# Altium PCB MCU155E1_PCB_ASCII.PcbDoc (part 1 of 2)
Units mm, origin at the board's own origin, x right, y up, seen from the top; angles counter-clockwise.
Board outline 32 x 29 mm, 4 copper layers (Top Layer, Layer 1, Layer 2, Bottom Layer), stack 1.567 mm thick; 102 components, 61 nets, 283 pads, 120 vias.
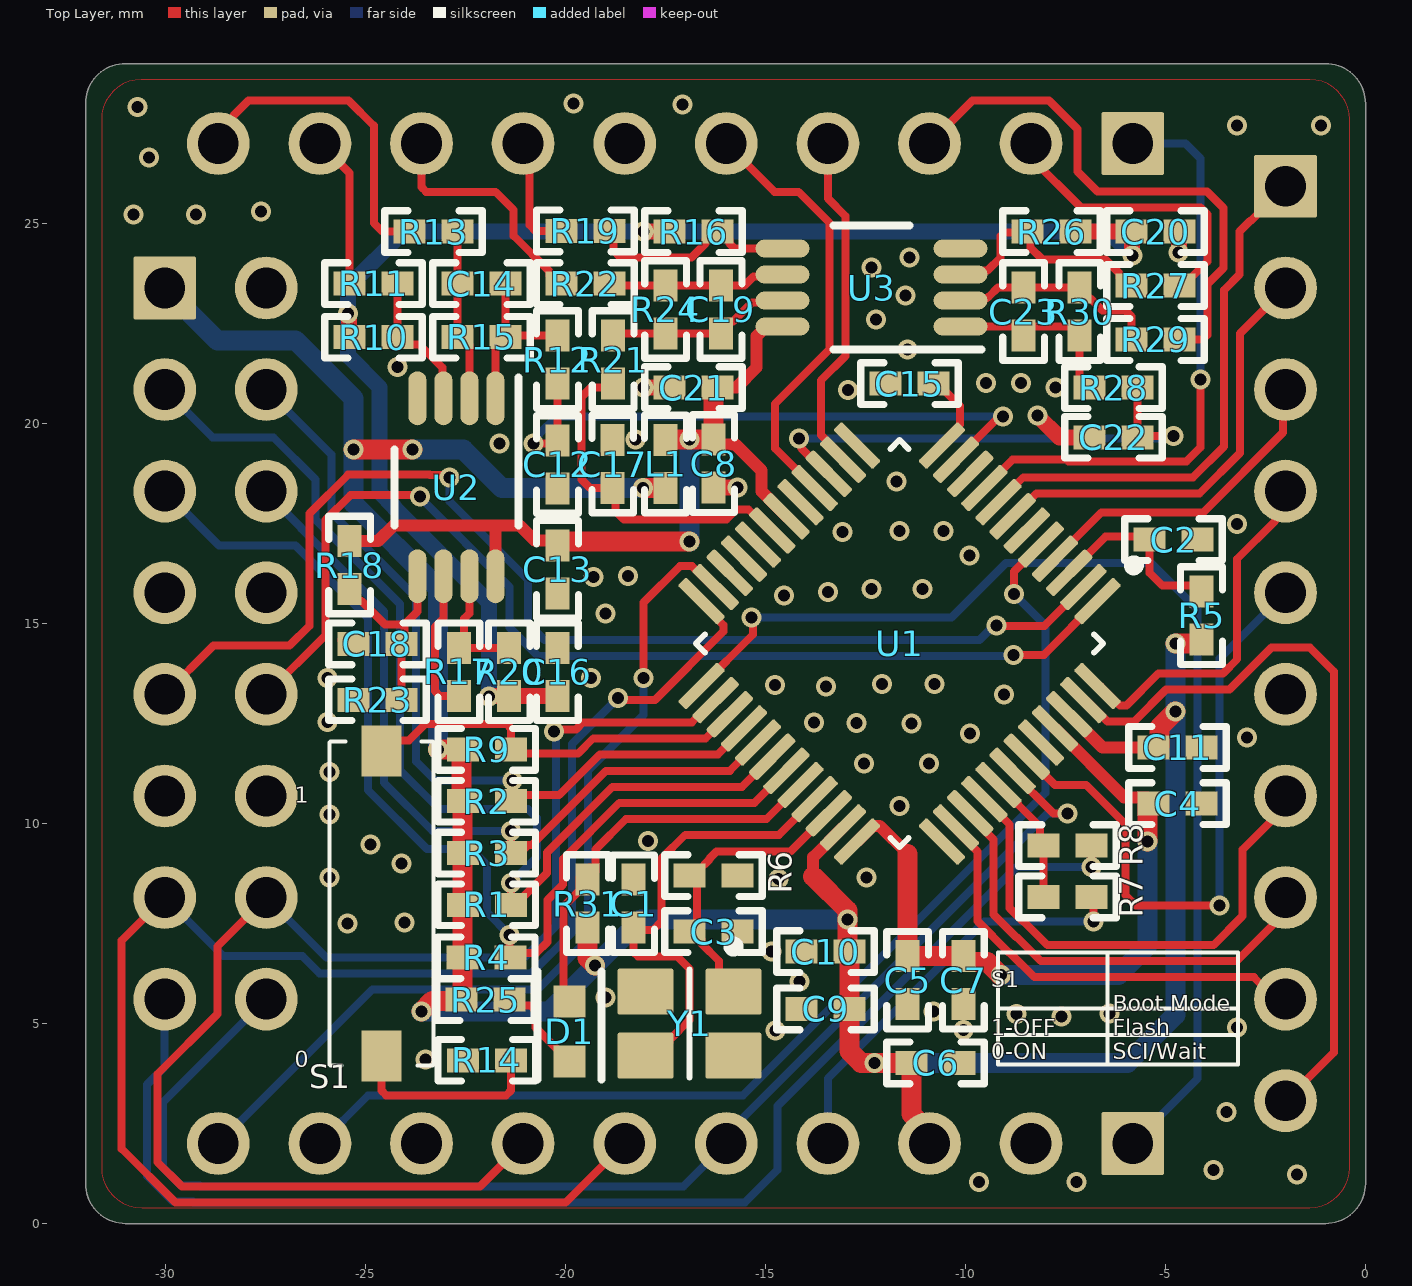
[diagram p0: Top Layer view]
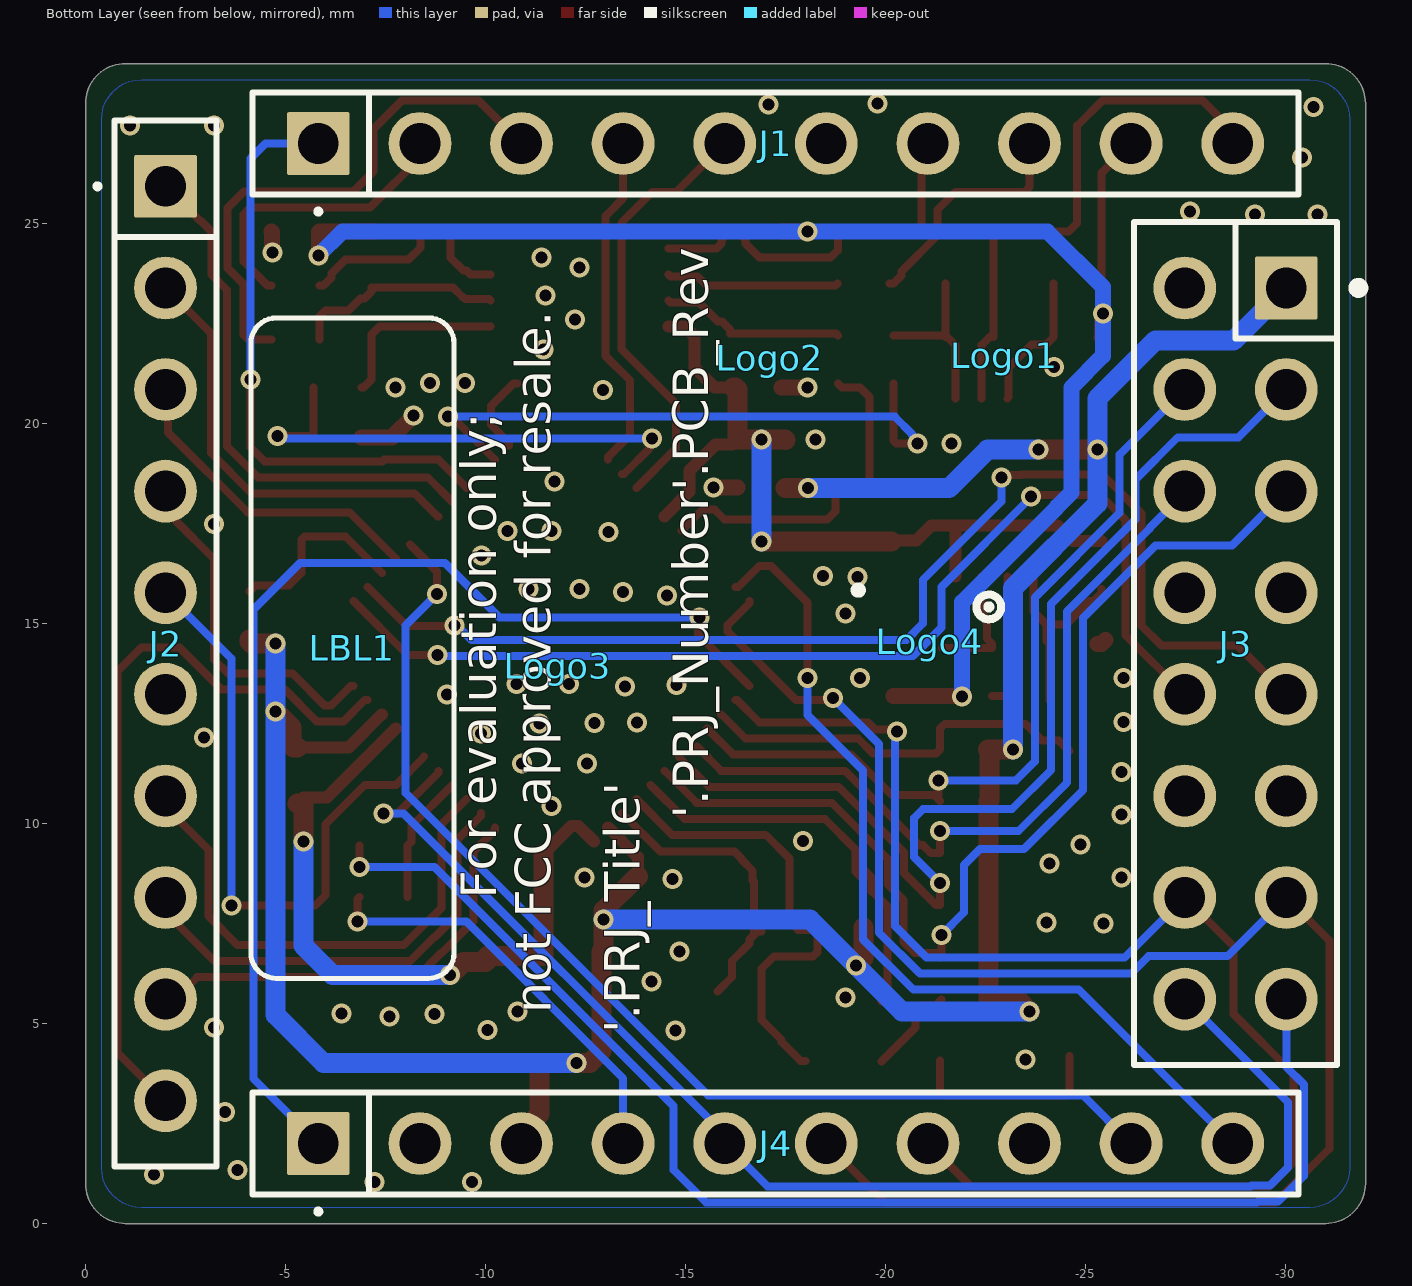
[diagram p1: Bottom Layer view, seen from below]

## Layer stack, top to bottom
Top Solder: solder mask 0.0102, Solder Resist, Dk 3.5
Top Layer: signal copper 0.035
Dielectric 1: prepreg 0.2184, PP-023, Dk 4.5
Layer 1: signal copper 0.035
Dielectric1: core 0.9906, Core-042, Dk 4.6
Layer 2: signal copper 0.035
Dielectric 2: prepreg 0.2184, PP-023, Dk 4.5
Bottom Layer: signal copper 0.035
Bottom Solder: solder mask 0.0102, Solder Resist, Dk 3.5

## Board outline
-32,1 -32,28 cw(c-31,28) -31,29 -1,29 cw(c-1,28) 0,28 0,1 cw(c-1,1) -1,0 -31,0 cw(c-31,1)

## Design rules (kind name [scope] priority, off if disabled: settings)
AcuteAngle [All] p0: scope1count=1 scope1_0_kind=Board scope1_0_value=Board scope2count=1 scope2_0_kind=Board scope2_0_value=Board commentlength=0 minimum=4.50000000000000E+0001
AcuteAngle [All] p1: minimum=4.50000000000000E+0001 checktracksonly=FALSE
AssemblyTestPointUsage [All] p0: scope1count=1 scope1_0_kind=Board scope1_0_value=Board scope2count=1 scope2_0_kind=Board scope2_0_value=Board commentlength=0
AssemblyTestPointUsage [All] p1: valid=2
AssemblyTestpoint [All] p0: scope1count=1 scope1_0_kind=Board scope1_0_value=Board scope2count=1 scope2_0_kind=Board scope2_0_value=Board commentlength=0
BoardOutlineClearance [All] p0 off: scope1count=1 scope1_0_kind=Board scope1_0_value=Board scope2count=1 scope2_0_kind=Board scope2_0_value=Board commentlength=172 gap=0 // Protel DXP Scope 1 Expression Was: OnCopper and Not InComponentClass('Logo') and not InComponentClass('FiducialMark') and not InRegion(1000,500,4000,800) and not InPoly
BoardOutlineClearance BoardOutlineClearance_Poly [All] p0 off: scope1count=1 scope1_0_kind=Board scope1_0_value=Board scope2count=1 scope2_0_kind=Board scope2_0_value=Board commentlength=58 gap=0 // Protel DXP Scope 1 Expression Was: OnCopper and IsPoly
BoardOutlineClearance BoardOutlineClearance_MountingHoles [All] p0 off: scope1count=1 scope1_0_kind=Board scope1_0_value=Board scope2count=1 scope2_0_kind=Board scope2_0_value=Board commentlength=86 gap=0 // Protel DXP Scope 1 Expression Was: OnCopper and InComponentClass('Mounting Holes')
BoardOutlineClearance BoardOutlineClearance_MountingHoles [OnCopper and InComponentClass('Mounting Holes')] p1: gap=0 ignorepadtopadclearanceinfootprint=FALSE
BoardOutlineClearance BoardOutlineClearance_Poly [OnCopper and IsPoly] p2: gap=0 ignorepadtopadclearanceinfootprint=FALSE
BoardOutlineClearance [OnCopper and Not InComponentClass('Logo') and not InComponentClass('FiducialMark') and not InRegion(1000,500,4000,800) and not InPoly] p3: gap=0 ignorepadtopadclearanceinfootprint=FALSE
Clearance Clearance_1 [All] p0 off: scope1count=1 scope1_0_kind=Board scope1_0_value=Board scope2count=1 scope2_0_kind=Board scope2_0_value=Board commentlength=160 gap=0.19 // Protel DXP Scope 1 Expression Was: (InComponent('J1') or InComponent('J2') or InComponent('J3') or InComponent('J4') ) and not HasFootprint('fiducial10-20')
Clearance [All] p0 off: scope1count=1 scope1_0_kind=Board scope1_0_value=Board scope2count=1 scope2_0_kind=Board scope2_0_value=Board commentlength=159 gap=0.2 // Protel DXP Scope 2 Expression Was: not HasFootprint('fiducial10-20') or (InComponent('J1') or InComponent('J2') or InComponent('J3') or InComponent('J4') )
Clearance SMTPadToTHHole [All] p0 off: scope1count=1 scope1_0_kind=Board scope1_0_value=Board scope2count=1 scope2_0_kind=Board scope2_0_value=Board commentlength=115 gap=0.15 // Protel DXP Scope 2 Expression Was: InSMTComponent and OnLayer('Bottom Layer') and not HasFootprint('TP_SM_1MM')
Clearance PB+ToPB- [All] p0: scope1count=1 scope1_0_kind=NetClass scope1_0_value=HV scope2count=1 scope2_0_kind=NetClass scope2_0_value=LV_Signal commentlength=0 gap=3
Clearance PB+ToACN [All] p0: scope1count=1 scope1_0_kind=NetClass scope1_0_value=V_BUS scope2count=1 scope2_0_kind=NetClass scope2_0_value=ACN commentlength=0 gap=1.5
Clearance PB+ToACL [All] p0: scope1count=1 scope1_0_kind=NetClass scope1_0_value=V_BUS scope2count=1 scope2_0_kind=NetClass scope2_0_value=ACL commentlength=0 gap=3
Clearance PB-ToACL [All] p0: scope1count=1 scope1_0_kind=NetClass scope1_0_value="LV Signal" scope2count=1 scope2_0_kind=NetClass scope2_0_value=ACL commentlength=0 gap=3
Clearance ISOToAll [All] p0 off: scope1count=1 scope1_0_kind=NetClass scope1_0_value=Isolation scope2count=1 scope2_0_kind=Board scope2_0_value=Board commentlength=105 gap=6 // Protel DXP Scope 2 Expression Was: not InNetClass('Isolation')   and (not  OnLayer('Keep-Out Layer'))
Clearance ACLToACN [All] p0: scope1count=1 scope1_0_kind=NetClass scope1_0_value=ACL scope2count=1 scope2_0_kind=NetClass scope2_0_value=ACN commentlength=0 gap=2
Clearance PB-ToACN [All] p0: scope1count=1 scope1_0_kind=NetClass scope1_0_value="LV Signal" scope2count=1 scope2_0_kind=NetClass scope2_0_value=ACN commentlength=0 gap=3
Clearance Clearance_1 [(InComponent('J1') or InComponent('J2') or InComponent('J3') or InComponent('J4') ) and not HasFootprint('fiducial10-20')] p1: gap=0.19 ignorepadtopadclearanceinfootprint=TRUE
Clearance PB+ToPB- [InNetClass('HV') vs InNetClass('LV_Signal')] p2: gap=3 ignorepadtopadclearanceinfootprint=TRUE
Clearance PB-ToACN [InNetClass('LV Signal') vs InNetClass('ACN')] p3: gap=3 ignorepadtopadclearanceinfootprint=TRUE
Clearance ACLToACN [InNetClass('ACL') vs InNetClass('ACN')] p4: gap=2 ignorepadtopadclearanceinfootprint=FALSE
Clearance ISOToAll [InNetClass('Isolation') vs not InNetClass('Isolation')   and (not  OnLayer('Keep-Out Layer'))] p5: gap=6 ignorepadtopadclearanceinfootprint=TRUE
Clearance PB-ToACL [InNetClass('LV Signal') vs InNetClass('ACL')] p6: gap=3 ignorepadtopadclearanceinfootprint=TRUE
Clearance PB+ToACL [InNetClass('V_BUS') vs InNetClass('ACL')] p7: gap=3 ignorepadtopadclearanceinfootprint=TRUE
Clearance PB+ToACN [InNetClass('V_BUS') vs InNetClass('ACN')] p8: gap=1.5 ignorepadtopadclearanceinfootprint=TRUE
Clearance SMTPadToTHHole [not IsVia and OnLayer('Multi-Layer') and not InComponent('J1') and not InComponent('J2') and not InComponent('J3') and not InComponent('J4') and not InComponent('J12') and PadIsPlated vs InSMTComponent and OnLayer('Bottom Layer') and not HasFootprint('TP_SM_1MM')] p9: gap=0.15 ignorepadtopadclearanceinfootprint=FALSE except(3: SMDPad-THPad)
Clearance [All vs not HasFootprint('fiducial10-20') or (InComponent('J1') or InComponent('J2') or InComponent('J3') or InComponent('J4') )] p10: gap=0.2 ignorepadtopadclearanceinfootprint=TRUE
ComponentClearance [All] p0: scope1count=1 scope1_0_kind=Board scope1_0_value=Board scope2count=1 scope2_0_kind=Board scope2_0_value=Board commentlength=0 gap=0.508 collisioncheckmode=3
ComponentClearance ComponentClearance_THtoTH [All] p0 off: scope1count=1 scope1_0_kind=Board scope1_0_value=Board scope2count=1 scope2_0_kind=Board scope2_0_value=Board commentlength=54 gap=0.508 collisioncheckmode=3 // Protel DXP Scope 2 Expression Was: IsThruComponent
ComponentClearance ComponentClearance_THtoSMT [All] p0 off: scope1count=1 scope1_0_kind=Board scope1_0_value=Board scope2count=1 scope2_0_kind=Board scope2_0_value=Board commentlength=53 gap=0.762 collisioncheckmode=3 // Protel DXP Scope 2 Expression Was: IsSMTComponent
ComponentClearance ComponentClearance_SmallPassives [All] p0 off: scope1count=1 scope1_0_kind=Board scope1_0_value=Board scope2count=1 scope2_0_kind=Board scope2_0_value=Board commentlength=508 gap=0.38 collisioncheckmode=3 // Protel DXP Scope 2 Expression Was: HasFootprint('0201*') or HasFootprint('0402*') or HasFootprint('0508') or HasFootprint('0603*') or HasFootprint('0612') or HasFootprint('0805*') or HasFootprint('0815*') or HasFootprint('0830*') or HasFootprint('1206*') or HasFootprint('1210*') or HasFootprint('1808*') or HasFootprint('1812*') or HasFootprint('1825*') or HasFootprint('2010*') or HasFootprint('2220*') or HasFootprint('2225*') or HasFootprint('2512*') or HasFootprint('2728*') or HasFootprint('3518*')
ComponentClearance ComponentClearance_MountingHoles [All] p0: scope1count=1 scope1_0_kind=ComponentClass scope1_0_value="Mounting Holes" scope2count=1 scope2_0_kind=Board scope2_0_value=Board commentlength=0 gap=2.54 collisioncheckmode=3
ComponentClearance ComponentClearance_ScrewToNut [All] p0 off: scope1count=1 scope1_0_kind=Board scope1_0_value=Board scope2count=1 scope2_0_kind=Board scope2_0_value=Board commentlength=71 gap=0.127 collisioncheckmode=3 // Protel DXP Scope 2 Expression Was: (HasFootprint('Keystone_1902C'))
ComponentClearance ComponentClearance_Logo [All] p0: scope1count=1 scope1_0_kind=ComponentClass scope1_0_value=Logo scope2count=1 scope2_0_kind=Board scope2_0_value=Board commentlength=0 gap=0.762 collisioncheckmode=3
ComponentClearance ComponentClearance_Shunt [All] p0: scope1count=1 scope1_0_kind=ComponentClass scope1_0_value=Header scope2count=1 scope2_0_kind=ComponentClass scope2_0_value=Shunt commentlength=0 gap=0 collisioncheckmode=3
ComponentClearance ComponentClearance_MountingHoles_FiducialMarks [All] p0: scope1count=1 scope1_0_kind=ComponentClass scope1_0_value="Mounting Holes" scope2count=1 scope2_0_kind=ComponentClass scope2_0_value=FiducialMark commentlength=0 gap=1.27 collisioncheckmode=3
ComponentClearance ComponentClearance_MountingHoles_FiducialMarks [InComponentClass('Mounting Holes') vs InComponentClass('FiducialMark')] p1: gap=1.27 collisioncheckmode=3 verticalgap=0.254 showdistances=FALSE
ComponentClearance ComponentClearance_Shunt [InComponentClass('Header') vs InComponentClass('Shunt')] p2: gap=0 collisioncheckmode=3 verticalgap=0 showdistances=FALSE
ComponentClearance ComponentClearance_Logo [InComponentClass('Logo')] p3: gap=0.762 collisioncheckmode=3 verticalgap=0.254 showdistances=FALSE
ComponentClearance ComponentClearance_ScrewToNut [(HasFootprint('NY PMS 440 0025 PH')) vs (HasFootprint('Keystone_1902C'))] p4: gap=0.127 collisioncheckmode=3 verticalgap=0.254 showdistances=FALSE
ComponentClearance ComponentClearance_MountingHoles [InComponentClass('Mounting Holes')] p5: gap=2.54 collisioncheckmode=3 verticalgap=2540 showdistances=FALSE
ComponentClearance ComponentClearance_SmallPassives [HasFootprint('0201*') or HasFootprint('0402*') or HasFootprint('0508') or HasFootprint('0603*') or HasFootprint('0612') or HasFootprint('0805*') or HasFootprint('0815*') or HasFootprint('0830*') or HasFootprint('1206*') or HasFootprint('1210*') or HasFootprint('1808*') or HasFootprint('1812*') or HasFootprint('1825*') or HasFootprint('2010*') or HasFootprint('2220*') or HasFootprint('2225*') or HasFootprint('2512*') or HasFootprint('2728*') or HasFootprint('3518*') vs HasFootprint('0201*') or HasFootprint('0402*') or HasFootprint('0508') or HasFootprint('0603*') or HasFootprint('0612') or HasFootprint('0805*') or HasFootprint('0815*') or HasFootprint('0830*') or HasFootprint('1206*') or HasFootprint('1210*') or HasFootprint('1808*') or HasFootprint('1812*') or HasFootprint('1825*') or HasFootprint('2010*') or HasFootprint('2220*') or HasFootprint('2225*') or HasFootprint('2512*') or HasFootprint('2728*') or HasFootprint('3518*')] p6: gap=0.38 collisioncheckmode=3 verticalgap=0.254 showdistances=FALSE
ComponentClearance ComponentClearance_THtoSMT [IsThruComponent vs IsSMTComponent] p7: gap=0.762 collisioncheckmode=3 verticalgap=0.762 showdistances=FALSE
ComponentClearance ComponentClearance_THtoTH [IsThruComponent vs IsThruComponent] p8: gap=0.508 collisioncheckmode=3 verticalgap=0.762 showdistances=FALSE
ComponentClearance [All] p9: gap=0.508 collisioncheckmode=3 verticalgap=0.254 showdistances=FALSE
DiffPairsRouting [All] p0: scope1count=1 scope1_0_kind=Board scope1_0_value=Board scope2count=1 scope2_0_kind=Board scope2_0_value=Board commentlength=0
DiffPairsRouting [All] p1: maxlimit=2.54 minlimit=0.254 mostfreqgap=0.254 toplayer_minwidth=0.381 toplayer_maxwidth=0.381 toplayer_prefwidth=0.381 midlayer1_minwidth=0.381 midlayer1_maxwidth=0.381 midlayer1_prefwidth=0.381 midlayer2_minwidth=0.381 midlayer2_maxwidth=0.381 midlayer2_prefwidth=0.381 bottomlayer_minwidth=0.381 bottomlayer_maxwidth=0.381 bottomlayer_prefwidth=0.381 maxuncoupledlength=25.4
FabricationTestPointUsage TestPointUsage [All] p0: scope1count=1 scope1_0_kind=Board scope1_0_value=Board scope2count=1 scope2_0_kind=Board scope2_0_value=Board commentlength=0 valid=2 allowmultiple=FALSE
FabricationTestPointUsage TestPointUsage [All] p1: valid=2 allowmultiple=FALSE
FabricationTestpoint Testpoint [All] p0: scope1count=1 scope1_0_kind=Board scope1_0_value=Board scope2count=1 scope2_0_kind=Board scope2_0_value=Board commentlength=0 side=3 testpointundercomponent=TRUE minsize=1.016 maxsize=2.54 preferedsize=1.524 minholesize=0 maxholesize=1.016 preferedholesize=0.813 testpointgrid=0.025
FabricationTestpoint Testpoint [All] p1: side=3 testpointundercomponent=TRUE minsize=1.016 maxsize=2.54 preferedsize=1.524 minholesize=0 maxholesize=1.016 preferedholesize=0.813 testpointgrid=0.025 allowsidetop=TRUE allowsidebottom=TRUE usegrid=TRUE gridtolerance=0
FanoutControl Fanout_Small [All] p0 off: scope1count=1 scope1_0_kind=Board scope1_0_value=Board scope2count=1 scope2_0_kind=Board scope2_0_value=Board commentlength=84 // Protel DXP Scope 1 Expression Was: (CompPinCount < 5)   Fanout_Small (Default Rule)
FanoutControl Fanout_Default [All] p0: scope1count=1 scope1_0_kind=Board scope1_0_value=Board scope2count=1 scope2_0_kind=Board scope2_0_value=Board commentlength=30 // Fanout_Default (Default Rule)
FanoutControl Fanout_SOIC [All] p0 off: scope1count=1 scope1_0_kind=Board scope1_0_value=Board scope2count=1 scope2_0_kind=Board scope2_0_value=Board commentlength=71 // Protel DXP Scope 1 Expression Was: IsSOIC   Fanout_SOIC (Default Rule)
FanoutControl Fanout_BGA [All] p0 off: scope1count=1 scope1_0_kind=Board scope1_0_value=Board scope2count=1 scope2_0_kind=Board scope2_0_value=Board commentlength=69 // Protel DXP Scope 1 Expression Was: IsBGA   Fanout_BGA (Default Rule)
FanoutControl Fanout_LCC [All] p0 off: scope1count=1 scope1_0_kind=Board scope1_0_value=Board scope2count=1 scope2_0_kind=Board scope2_0_value=Board commentlength=69 // Protel DXP Scope 1 Expression Was: IsLCC   Fanout_LCC (Default Rule)
FanoutControl Fanout_LCC [IsLCC] p1: bgadir=Out bgaviamode=Centered fanoutstyle=Auto fanoutdirection=Alternating viagrid=0.025 // Fanout_LCC (Default Rule)
FanoutControl Fanout_BGA [IsBGA] p2: bgadir=Out bgaviamode=Centered fanoutstyle=Auto fanoutdirection=Alternating viagrid=0.025 // Fanout_BGA (Default Rule)
FanoutControl Fanout_Default [All] p4: bgadir=Out bgaviamode=Centered fanoutstyle=Auto fanoutdirection=Alternating viagrid=0.025 // Fanout_Default (Default Rule)
FanoutControl Fanout_Small [(CompPinCount < 5)] p5: bgadir=Out bgaviamode=Centered fanoutstyle=Auto fanoutdirection=OutThenIn viagrid=0.025 // Fanout_Small (Default Rule)
Height [All] p0: scope1count=1 scope1_0_kind=Board scope1_0_value=Board scope2count=1 scope2_0_kind=Board scope2_0_value=Board commentlength=0
HoleSize [All] p0: scope1count=1 scope1_0_kind=Board scope1_0_value=Board scope2count=1 scope2_0_kind=Board scope2_0_value=Board commentlength=0 absolutevalues=TRUE maxlimit=6.375 minlimit=0.2 maxpercent=80.000 minpercent=20.000
HoleSize [All] p1: absolutevalues=TRUE maxlimit=6.375 minlimit=0.2 maxpercent=80.000 minpercent=20.000
HoleToHoleClearance [All] p0: scope1count=1 scope1_0_kind=Board scope1_0_value=Board scope2count=1 scope2_0_kind=Board scope2_0_value=Board commentlength=0
LayerPairs [All] p0: scope1count=1 scope1_0_kind=Board scope1_0_value=Board scope2count=1 scope2_0_kind=Board scope2_0_value=Board commentlength=0 enforce=TRUE
MinimumAnnularRing [All] p0: scope1count=1 scope1_0_kind=Board scope1_0_value=Board scope2count=1 scope2_0_kind=Board scope2_0_value=Board commentlength=0 minimumring=0.2
MinimumAnnularRing MinimumAnnularRing_ThermalPadVias [All] p0 off: scope1count=1 scope1_0_kind=Board scope1_0_value=Board scope2count=1 scope2_0_kind=Board scope2_0_value=Board commentlength=63 minimumring=0.15 // Protel DXP Scope 1 Expression Was: IsVia and InAnyComponent
MinimumAnnularRing MinimumAnnularRing_ThermalPadVias [IsVia and InAnyComponent] p1: minimumring=0.15
MinimumAnnularRing [All] p2: minimumring=0.2
MinimumSolderMaskSliver [All] p0: scope1count=1 scope1_0_kind=Board scope1_0_value=Board scope2count=1 scope2_0_kind=Board scope2_0_value=Board commentlength=0
MinimumSolderMaskSliver MinimumSolderMaskSliver_Logo [All] p0: scope1count=1 scope1_0_kind=ComponentClass scope1_0_value=Logo scope2count=1 scope2_0_kind=ComponentClass scope2_0_value=Logo commentlength=0
MinimumSolderMaskSliver MinimumSolderMaskSliver_Logo [InComponentClass('Logo') vs InComponentClass('Logo')] p1: minsoldermaskwidth=0.018
MinimumSolderMaskSliver [All] p2: minsoldermaskwidth=0.1
NetAntennae [All] p0: scope1count=1 scope1_0_kind=Board scope1_0_value=Board scope2count=1 scope2_0_kind=Board scope2_0_value=Board commentlength=0
PasteMaskExpansion [All] p0: scope1count=1 scope1_0_kind=Board scope1_0_value=Board scope2count=1 scope2_0_kind=Board scope2_0_value=Board commentlength=0 expansion=0
PlaneClearance [All] p0: scope1count=1 scope1_0_kind=Board scope1_0_value=Board scope2count=1 scope2_0_kind=Board scope2_0_value=Board commentlength=0 clearance=0.508
PlaneConnect [All] p0: scope1count=1 scope1_0_kind=Board scope1_0_value=Board scope2count=1 scope2_0_kind=Board scope2_0_value=Board commentlength=0 planeconnectstyle=Direct reliefexpansion=0.254 reliefentries=4 reliefconductorwidth=0.254 reliefairgap=0.254
PlaneConnect [All] p1: planeconnectstyle=Direct reliefexpansion=0.254 reliefentries=4 reliefconductorwidth=0.254 reliefairgap=0.254
PolygonConnect "Thermal relief" [All] p0 off: scope1count=1 scope1_0_kind=Board scope1_0_value=Board scope2count=1 scope2_0_kind=Board scope2_0_value=Board commentlength=89 connectstyle=Relief reliefconductorwidth=0.5 reliefentries=4 polygonreliefangle="90 Angle" // Protel DXP Scope 2 Expression Was: InNet('GND') or innet('GND_ISO')  or innet('ubus')
PolygonConnect [All] p0: scope1count=1 scope1_0_kind=Board scope1_0_value=Board scope2count=1 scope2_0_kind=Board scope2_0_value=Board commentlength=0 connectstyle=Direct reliefconductorwidth=0.254 reliefentries=4 polygonreliefangle="90 Angle"
PolygonConnect "Thermal relief" [All vs InNet('GND') or innet('GND_ISO')  or innet('ubus')] p1: thpad.connectstyle=Relief thpad.reliefconductorwidth=0.5 thpad.reliefentries=4 thpad.polygonreliefangle="90 Angle" thpad.airgapwidth=0.254 smdpad.connectstyle=Direct smdpad.reliefconductorwidth=0.5 smdpad.reliefentries=4 smdpad.polygonreliefangle="90 Angle" smdpad.airgapwidth=0.254 via.connectstyle=Direct via.reliefconductorwidth=0.5 via.reliefentries=4 via.polygonreliefangle="90 Angle" via.airgapwidth=0.254
PolygonConnect [All] p2: connectstyle=Direct reliefconductorwidth=0.254 reliefentries=4 polygonreliefangle="90 Angle" airgapwidth=0.254
RoutingCorners [All] p0: scope1count=1 scope1_0_kind=Board scope1_0_value=Board scope2count=1 scope2_0_kind=Board scope2_0_value=Board commentlength=0 cornerstyle=45-Degree minsetback=2.54 maxsetback=2.54
RoutingLayers [All] p0: scope1count=1 scope1_0_kind=Board scope1_0_value=Board scope2count=1 scope2_0_kind=Board scope2_0_value=Board commentlength=0 top layer=Automatic mid layer 1=Automatic mid layer 2=Automatic bottom layer=Automatic
RoutingPriority [All] p0: scope1count=1 scope1_0_kind=Board scope1_0_value=Board scope2count=1 scope2_0_kind=Board scope2_0_value=Board commentlength=0
RoutingTopology [All] p0: scope1count=1 scope1_0_kind=Board scope1_0_value=Board scope2count=1 scope2_0_kind=Board scope2_0_value=Board commentlength=0 topology=Shortest
RoutingVias [All] p0: scope1count=1 scope1_0_kind=Board scope1_0_value=Board scope2count=1 scope2_0_kind=Board scope2_0_value=Board commentlength=0 holewidth=0.2 width=0.5 viastyle="Through Hole" minholewidth=0.2 minwidth=0.4 maxholewidth=1 maxwidth=1.4
RoutingVias ThermalPadVias [All] p0 off: scope1count=1 scope1_0_kind=Board scope1_0_value=Board scope2count=1 scope2_0_kind=Board scope2_0_value=Board commentlength=63 holewidth=0.2 width=0.5 viastyle="Through Hole" minholewidth=0.2 minwidth=0.5 maxholewidth=0.33 maxwidth=0.6 // Protel DXP Scope 1 Expression Was: IsVia and InAnyComponent
RoutingVias ThermalPadVias [IsVia and InAnyComponent] p1: holewidth=0.2 width=0.5 viastyle="Through Hole" minholewidth=0.2 minwidth=0.5 maxholewidth=0.33 maxwidth=0.6
RoutingVias [All] p2: holewidth=0.2 width=0.5 viastyle="Through Hole" minholewidth=0.2 minwidth=0.4 maxholewidth=1 maxwidth=1.4
ShortCircuit [All] p0: scope1count=1 scope1_0_kind=Board scope1_0_value=Board scope2count=1 scope2_0_kind=Board scope2_0_value=Board commentlength=0 allowed=FALSE
SilkToBoardRegionClearance [All] p0 off: scope1count=1 scope1_0_kind=Board scope1_0_value=Board scope2count=1 scope2_0_kind=Board scope2_0_value=Board commentlength=130 // Protel DXP Scope 1 Expression Was: Not ((IsComment or IsDesignator) And (Hide <> 'False')) and not InRegion(1000,500,4000,800)
SilkToBoardRegionClearance [Not ((IsComment or IsDesignator) And (Hide <> 'False')) and not InRegion(1000,500,4000,800)] p1:
SilkToSilkClearance [All] p0: scope1count=1 scope1_0_kind=Board scope1_0_value=Board scope2count=1 scope2_0_kind=Board scope2_0_value=Board commentlength=0
SilkToSilkClearance SilkToSilkClearance_Pb-FreeLogo [All] p0 off: scope1count=1 scope1_0_kind=Board scope1_0_value=Board scope2count=1 scope2_0_kind=Board scope2_0_value=Board commentlength=120 // Protel DXP Scope 2 Expression Was: (HasFootprint('Pb-Free_Overlay_Medium') OR HasFootprint('Pb-Free_Overlay_Small'))
SilkToSilkClearance SilkToSilkClearance_Pb-FreeLogo [(HasFootprint('Pb-Free_Overlay_Medium') OR HasFootprint('Pb-Free_Overlay_Small')) vs (HasFootprint('Pb-Free_Overlay_Medium') OR HasFootprint('Pb-Free_Overlay_Small'))] p1: silktosilkclearance=0
SilkToSilkClearance [All] p2: silktosilkclearance=0.1
SilkToSolderMaskClearance "Silk to Solder Mask Opening" [All] p0: scope1count=1 scope1_0_kind=Board scope1_0_value=Board scope2count=1 scope2_0_kind=Board scope2_0_value=Board commentlength=0
SilkToSolderMaskClearance SilkToComponentPadClearance [All] p0 off: scope1count=1 scope1_0_kind=Board scope1_0_value=Board scope2count=1 scope2_0_kind=Board scope2_0_value=Board commentlength=87 // Protel DXP Scope 1 Expression Was: (IsPad or IsFill or IsRegion) and InAnycomponent
SilkToSolderMaskClearance SilkToComponentPadClearance [(IsPad or IsFill or IsRegion) and InAnycomponent] p1: minsilkscreentomaskgap=0.127 clearancetoexposedcopper=TRUE
SilkToSolderMaskClearance "Silk to Solder Mask Opening" [All] p2: minsilkscreentomaskgap=0.1 clearancetoexposedcopper=FALSE
SolderMaskExpansion [All] p0: scope1count=1 scope1_0_kind=Board scope1_0_value=Board scope2count=1 scope2_0_kind=Board scope2_0_value=Board commentlength=0 expansion=0.05
SolderMaskExpansion [All] p1: expansion=0.05 istentingtop=FALSE
UnRoutedNet [All] p0: scope1count=1 scope1_0_kind=Board scope1_0_value=Board scope2count=1 scope2_0_kind=Board scope2_0_value=Board commentlength=0
UnRoutedNet [All] p1: checkbadconnections=TRUE
UnpouredPolygon [All] p0: scope1count=1 scope1_0_kind=Board scope1_0_value=Board scope2count=1 scope2_0_kind=Board scope2_0_value=Board commentlength=0
Width [All] p0: scope1count=1 scope1_0_kind=Board scope1_0_value=Board scope2count=1 scope2_0_kind=Board scope2_0_value=Board commentlength=0 maxlimit=5 minlimit=0.2 preferedwidth=0.3
Width [All] p1: maxlimit=5 minlimit=0.2 preferedwidth=0.3 minimp=50.000000 maximp=50.000000 favimp=50.000000 checkconnectedcopper=TRUE
14 further rules are at their usual default settings.

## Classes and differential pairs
component class Logo: Logo2
component class Label: LBL1
component class TIEVM-MC-MODULE-F280013x: C1 C2 C3 C4 C5 C6 C7 C8 C9 C10 C11 C12 C13 C14 C15 C16 C17 C18 C19 C20 C21 C22 C23 D1 J1 J2 J3 J4 L1 LBL1 Logo1 Logo2 Logo3 Logo4 R1 R2 R3 R4 R5 R6 R7 R8 R9 R10 R11 R12 R13 R14 R15 R16 R17 R18 R19 R20 R21 R22 R23 R24 R25 R26 R27 R28 R29 R30 R31 S1 U1 U2 U3 Y1

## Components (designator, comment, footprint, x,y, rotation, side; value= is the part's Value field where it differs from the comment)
C1 "GRM1555C1H120JA01D" 0402 -18.3,7.998 r270 top
C2 "GRM155R71C104KA88D" 0402 -4.8,17.1 r0 top
C3 "GRM1555C1H120JA01D" 0402 -16.3,7.3 r0 top
C4 "GRM155R71C104KA88D" 0402 -4.7,10.5 r180 top
C5 "GRM155R71C104KA88D" 0402 -11.448,6.083 r90 top
C6 "GRM155R61A106ME11" 0402 -10.75,4.015 r0 top
C7 "GRM155R61A106ME11" 0402 -10.051,6.083 r90 top
C8 "GRM155R61A106ME11" 0402 -16.3,19 r270 top
C9 "GRM155R61A106ME11" 0402 -13.5,5.366 r180 top
C10 "GRM155R71C104KA88D" 0402 -13.5,6.8 r180 top
C11 "GRM155R71C104KA88D" 0402 -4.7,11.901 r0 top
C12 "C1005C0G1H221F050BA" 0402 -20.2,18.977 r270 top
C13 "GRM155R71C104KA88D" 0402 -20.2,16.353 r270 top
C14 "GRM1555C1H101JA01D" 0402 -22.1,23.5 r0 top
C15 "GRM155R61A225ME95" 0402 -11.4,21 r180 top
C16 "GRM155R61C103KA01D" 0402 -20.201,13.793 r90 top
C17 "C1005C0G1H221F050BA" 0402 -18.82,18.988 r90 top
C18 "GRM155R71C104KA88D" 0402 -24.701,14.491 r180 top
C19 "GRM1555C1H101JA01D" 0402 -16.113,22.852 r270 top
C20 "GRM155R71C104KA88D" 0402 -5.25,24.8 r0 top
C21 "GRM155R71C104KA88D" 0402 -16.8,20.9 r180 top
C22 "C1005C0G1H221F050BA" 0402 -6.3,19.656 r180 top
C23 "GRM1555C1H101JA01D" 0402 -8.548,22.8 r270 top
D1 "LTST-C193KRKT-5A" LTST-C193_Red -19.9,4.8 r90 top
J1 "SSQ-110-03-T-S" FP-SSQ-110-03-T-S_CONN_RCPT10-MFG -17.25,27 r180 bottom
J2 "SSQ-110-03-T-S" FP-SSQ-110-03-T-S_CONN_RCPT10-MFG -2,14.5 r270 bottom locked
J3 "SSQ-108-03-T-D" FP-SSQ-108-03-T-D_HDR16-MFG -28.75,14.5 r270 bottom locked
J4 "SSQ-110-03-T-S" FP-SSQ-110-03-T-S_CONN_RCPT10-MFG -17.25,2 r180 bottom locked
L1 "782423100" 0402 -17.5,18.988 r90 top
LBL1 "THT-14-423-10" Label_650x200 -6.674,14.385 r270 bottom
Logo1 "CE Mark" CE_Mark_5mm -22.967,21.7 r90 bottom
Logo2 "Texas Instruments" TI_Symbol_Overlay_Small -17.1,21.65 r90 bottom
Logo3 "FCC disclaimer" FCC_disclaimer_stacked -11.8,13.95 r90 bottom
Logo4 "WEEE logo" WEEE_Minimum -21.1,14.55 r90 bottom
M44 "Comment" Arrow 343.55,113.9 r0 top
M45 "Comment" Arrow 386.55,113.9 r180 bottom
M46 "Comment" MARK 416.05,-5.6 r0 top
M47 "Comment" Toolinghole 401.05,-7.1 r0 top
M48 "Comment" "White oil-26X4" 322.05,111.9 r0 top
M49 "Comment" "Bad Mark" 386.05,-5.6 r0 top
M49 "Comment" MARK 411.05,-5.6 r0 top
M49_1 "Comment" "Bad Mark" 354.05,-5.6 r0 top
M49_2 "Comment" "Bad Mark" 322.05,-5.6 r0 top
M50 "Comment" MARK 266.05,-5.6 r0 top
M51 "Comment" MARK 266.05,112.4 r0 top
M52 "Comment" MARK 416.05,112.4 r0 top
M53 "Comment" Toolinghole 276.05,-7.1 r0 top
M54 "Comment" Toolinghole 276.05,113.9 r0 top
M55 "Comment" Toolinghole 406.05,113.9 r0 top
M56 "Comment" "Bad Mark" 381.05,-5.6 r0 top
M56_1 "Comment" "Bad Mark" 349.05,-5.6 r0 top
M56_2 "Comment" "Bad Mark" 317.05,-5.6 r0 top
M57 "Comment" "Bad Mark" 376.05,-5.6 r0 top
M57_1 "Comment" "Bad Mark" 344.05,-5.6 r0 top
M57_2 "Comment" "Bad Mark" 312.05,-5.6 r0 top
M57_2_1 "Comment" "Bad Mark" 302.05,-5.6 r0 top
M57_2_2 "Comment" "Bad Mark" 290.05,-5.6 r0 top
M58 "Comment" "Bad Mark" 371.05,-5.6 r0 top
M58_1 "Comment" "Bad Mark" 339.05,-5.6 r0 top
M58_2 "Comment" "Bad Mark" 307.05,-5.6 r0 top
M58_2_1 "Comment" "Bad Mark" 297.05,-5.6 r0 top
M59 "Comment" "Bad Mark" 366.05,-5.6 r0 top
M59_1 "Comment" "Bad Mark" 334.05,-5.6 r0 top
M60 "Comment" "Bad Mark" 361.05,-5.6 r0 top
M60_1 "Comment" "Bad Mark" 329.05,-5.6 r0 top
M61 "Comment" "Bad Mark" 393.05,-5.6 r0 top
R1 "ERJ-2RKF2401X" 0402 -21.965,7.967 r180 top
R2 "RC0402FR-0710KL" 0402 -21.965,10.557 r180 top
R3 "RC0402FR-0710KL" 0402 -21.965,9.262 r180 top
R4 "RC0402FR-0710KL" 0402 -21.981,6.647 r180 top
R5 "RC0402FR-0710KL" 0402 -4.1,15.2 r270 top
R6 "RG1005P-104-B-T5" 0402 -16.3,8.698 r180 top
R7 "RC0402JR-070RL" 0402 -7.45,8.165 r180 top
R8 "RC0402JR-070RL" 0402 -7.45,9.45 r180 top
R9 "CMP-0026949-3" 0402 -21.965,11.852 r180 top
R10 "RC0402FR-0710KL" 0402 -24.8,22.158 r180 top
R11 "ERJ-2RKF2401X" 0402 -24.8,23.5 r0 top
R12 "RC0402FR-07100RL" 0402 -20.2,21.6 r270 top
R13 "ERJ-2RKF2401X" 0402 -23.3,24.8 r0 top
R14 "CMP-0026890-5" 0402 -21.965,4.082 r180 top
R15 "RC0402FR-0710KL" 0402 -22.1,22.158 r0 top
R16 "RC0402FR-0710KL" 0402 -16.8,24.8 r180 top
R17 "RC0402FR-0710KL" 0402 -22.664,13.793 r270 top
R18 "RC0402FR-0710KL" 0402 -25.399,16.463 r90 top
R19 "ERJ-2RKF2401X" 0402 -19.501,24.814 r0 top
R20 "RC0402FR-07100RL" 0402 -21.407,13.793 r270 top
R21 "RC0402FR-07100RL" 0402 -18.811,21.6 r270 top
R22 "ERJ-2RKF2401X" 0402 -19.501,23.5 r0 top
R23 "RC0402FR-0710KL" 0402 -24.7,13.094 r0 top
R24 "RC0402FR-0710KL" 0402 -17.498,22.852 r270 top
R25 "RC0402FR-071KL" 0402 -22,5.6 r0 top
R26 "RC0402FR-0710KL" 0402 -7.85,24.8 r0 top
R27 "ERJ-2RKF2401X" 0402 -5.25,23.451 r180 top
R28 "RC0402FR-07100RL" 0402 -6.3,20.9 r0 top
R29 "ERJ-2RKF2401X" 0402 -5.25,22.101 r180 top
R30 "RC0402FR-0710KL" 0402 -7.146,22.8 r270 top
R31 "CMP-0026949-3" 0402 -19.45,8 r270 top
S1 "CHS-01TB" SW_CHS-01TB -24.6,8 r0 top
U1 "F2800137PT" PT0048A-MFG -11.65,14.5 r225 top locked
U2 "TLV9062IDGKR" DGK0008A_N -22.727,18.406 r270 top
U3 "TLV9062IDGKR" DGK0008A_N -12.35,23.4 r180 top
Y1 "830108207209" FP-830108207209_SMT_CRYSTAL_3MM2_2MM5-MFG -16.9,5 r180 top

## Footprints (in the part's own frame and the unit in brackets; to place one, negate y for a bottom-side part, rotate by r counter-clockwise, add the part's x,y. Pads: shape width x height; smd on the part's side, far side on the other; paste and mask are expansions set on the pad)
0402 [mm] "0402 from SM-752 data"
  rect 0.8x0.6 smd: 1(-0.6,0) 2(0.6,0)
  silkscreen extent -1.22,-0.52 1.22,0.52
Arrow [mm] "·½Ïò¼ýÍ·"
"Bad Mark" [mm]
  round 2 on Bottom Solder: 2(0,0)
  round 2 on Top Solder: 2(0,0)
CE_Mark_5mm [mm] "Minimum text height for CE Mark"
DGK0008A_N [mm] "TSOP, 8-Leads, Body 3x3mm, Pitch 0.65mm, IPC Medium Density"
  oval 1.35x0.45 smd: 1(-2.225,0.975) 2(-2.225,0.325) 3(-2.225,-0.325) 4(-2.225,-0.975) 5(2.225,-0.975) 6(2.225,-0.325) 7(2.225,0.325) 8(2.225,0.975)
  silkscreen extent -2.75,-1.55 0.95,1.55
FCC_disclaimer_stacked [mm]
FP-830108207209_SMT_CRYSTAL_3MM2_2MM5-MFG [mm]
  rrect9% 1.4x1.15 smd paste+0 mask+0: 1(-1.1,-0.8) 2(1.1,-0.8) 3(1.1,0.8) 4(-1.1,0.8)
  silkscreen extent -1.23,-2.05 0,1.35
FP-SSQ-108-03-T-D_HDR16-MFG [mm]
  rrect6% 1.57x1.57 hole 1.02 paste+0 mask+0: 1(-8.89,1.27)
  round 1.57 hole 1.02 paste+0 mask+0: 2(-8.89,-1.27) 3(-6.35,1.27) 4(-6.35,-1.27) 5(-3.81,1.27) 6(-3.81,-1.27) 7(-1.27,1.27) 8(-1.27,-1.27) 9(1.27,1.27) 10(1.27,-1.27) 11(3.81,1.27) 12(3.81,-1.27) 13(6.35,1.27) 14(6.35,-1.27) 15(8.89,1.27) 16(8.89,-1.27)
  silkscreen extent -10.54,-2.54 10.54,3.19
FP-SSQ-110-03-T-S_CONN_RCPT10-MFG [mm]
  rrect6% 1.57x1.57 hole 1.02 paste+0 mask+0: 1(-11.43,0)
  round 1.57 hole 1.02 paste+0 mask+0: 2(-8.89,0) 3(-6.35,0) 4(-3.81,0) 5(-1.27,0) 6(1.27,0) 7(3.81,0) 8(6.35,0) 9(8.89,0) 10(11.43,0)
  silkscreen extent -13.08,-1.76 13.08,1.27
Label_650x200 [mil] "Thermal Transfer Label"
  round 1 on Mech14: 0(0,0)
  silkscreen extent -325,-100 325,100
LTST-C193_Red [mm] "SMD, 2-Leads, Body1.6x0.8mm"
  rect 0.8x0.8 smd: 1(-0.75,0) 2(0.75,0)
  silkscreen extent -1.2,-0.8 1.5,0.8
MARK [mm]
  round 1 smd mask+0: 1(0,0)
  round 1 smd far side mask+0: 2(0,0)
PT0048A-MFG [mm]
  rrect33% 1.4x0.3 smd paste-1000 mask+0: 1(-4.25,2.75) 2(-4.25,2.25) 3(-4.25,1.75) 4(-4.25,1.25) 5(-4.25,0.75) 6(-4.25,0.25) 7(-4.25,-0.25) 8(-4.25,-0.75) 9(-4.25,-1.25) 10(-4.25,-1.75) 11(-4.25,-2.25) 12(-4.25,-2.75) 25(4.25,-2.75) 26(4.25,-2.25) 27(4.25,-1.75) 28(4.25,-1.25) 29(4.25,-0.75) 30(4.25,-0.25) 31(4.25,0.25) 32(4.25,0.75) 33(4.25,1.25) 34(4.25,1.75) 35(4.25,2.25) 36(4.25,2.75)
  rrect33% 0.3x1.4 smd paste-1000 mask+0: 13(-2.75,-4.25) 14(-2.25,-4.25) 15(-1.75,-4.25) 16(-1.25,-4.25) 17(-0.75,-4.25) 18(-0.25,-4.25) 19(0.25,-4.25) 20(0.75,-4.25) 21(1.25,-4.25) 22(1.75,-4.25) 23(2.25,-4.25) 24(2.75,-4.25) 37(2.75,4.25) 38(2.25,4.25) 39(1.75,4.25) 40(1.25,4.25) 41(0.75,4.25) 42(0.25,4.25) 43(-0.25,4.25) 44(-0.75,4.25) 45(-1.25,4.25) 46(-1.75,4.25) 47(-2.25,4.25) 48(-2.75,4.25)
  silkscreen extent -5.65,-3.6 3.6,3.6
SW_CHS-01TB [mm] "CHS Recommended footprint"
  rect 1x1.27 smd: 1(0,3.81) 2(0,-3.81)
  silkscreen extent -1.3,-4.05 1.3,4.05
TI_Symbol_Overlay_Small [mm]
Toolinghole [mm]
  round 2 hole 2 unplated: 1(0,0)
  silkscreen extent -1.41,-1.41 1.41,1.41
WEEE_Minimum [mm] "WEEElie bin"
  silkscreen extent 0.56,-1.79 1.38,1.88
"White oil-26X4" [mm] "¶þÎ¬Âë°×ÓÍ¿ò"
  silkscreen extent -26,0 0,4

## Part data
C1 C3: library part CMP-0006415-2, "CAP, CERM, 12 pF, 50 V, +/- 5%, C0G/NP0, 0402"
C2 C4 C5 C10 C11 C13 C18 C20 C21: library part CMP-0006641-2, "CAP, CERM, 0.1 uF, 16 V, +/- 10%, X7R, 0402"
C6 C7 C8 C9: library part CMP-0006564-1, "CAP, CERM, 10 uF, 10 V, +/- 20%, X5R, 0402"
C12 C17 C22: library part CMP-0006249-2, "CAP, CERM, 220 pF, 50 V, +/- 1%, C0G/NP0, 0402"
C14 C19 C23: library part CMP-0006410-2, "CAP, CERM, 100 pF, 50 V, +/- 5%, C0G/NP0, 0402"
C15: library part CMP-0006571-2, "CAP, CERM, 2.2 uF, 10 V, +/- 20%, X5R, 0402"
C16: library part CMP-0006590-2, "CAP, CERM, 0.01 uF, 16 V, +/- 10%, X5R, 0402"
D1: library part CMP-0079922-3, "LED, Red, SMD"
J1 J2 J4: library part CMP-0123041-2, "Conn Socket Strip SKT 10 POS 2.54mm Solder ST Top Entry Thru-Hole Bulk"
J3: library part CMP-0123022-2, "16 Position Receptacle Connector 0.100\" (2.54mm) Through Hole Tin"
L1: library part CMP-0003274-1, "Ferrite Bead, 10 ohm @ 100 MHz, 1.5 A, 0402"
LBL1: library part CMP-0003625-1, "Thermal Transfer Printable Labels, 0.650\" W x 0.200\" H - 10,000 per roll"
Logo1: library part CMP-0074844-1
Logo2: library part CMP-0074838-1, "Texas Instrument Corporate Signature"
Logo3: library part CMP-0074847-1, "FCC_disclaimer"
Logo4: library part CMP-0074769-1
R1 R11 R13 R19 R22 R27 R29: library part CMP-0026685-1, "RES, 2.40 k, 1%, 0.1 W, AEC-Q200 Grade 0, 0402"
R2 R3 R4 R5 R10 R15 R16 R17 R18 R23 R24 R26 R30: library part CMP-0078669-1, "RES, 10.0 k, 1%, 0.063 W, 0402"
R6: library part CMP-0026815-1, "RES, 100 k, 0.1%, 0.063 W, 0402"
R7 R8: library part CMP-0027004-2, "RES, 0, 5%, 0.063 W, 0402"
R9 R31: "RES, 56 k, 5%, 0.063 W, AEC-Q200 Grade 0, 0402"
R12 R20 R21 R28: library part CMP-0026722-1, "RES, 100, 1%, 0.063 W, 0402"
R14: "RES, 2.2 k, 5%, 0.063 W, AEC-Q200 Grade 0, 0402"
R25: library part CMP-0026725-1, "RES, 1.00 k, 1%, 0.0625 W, 0402"
S1: library part CMP-0002163-2, "Switch, Slide, SPST, Top Slide, SMT"
U1: library part CMP-0096487-1, "Real-Time Microcontrollers"
U2 U3: library part CMP-0084063-1, "10-MHz, Low-Noise, RRIO, CMOS Operational Amplifier for Cost-Sensitive Systems, DGK0008A (VSSOP-8)"
Y1: library part CMP-0093781-1, "20 MHz ±10ppm Crystal 8pF 50 Ohms 4-SMD, No Lead"

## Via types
v1: diameter 0.5, hole 0.3, Top Layer to Bottom Layer, tented both sides, 120 vias

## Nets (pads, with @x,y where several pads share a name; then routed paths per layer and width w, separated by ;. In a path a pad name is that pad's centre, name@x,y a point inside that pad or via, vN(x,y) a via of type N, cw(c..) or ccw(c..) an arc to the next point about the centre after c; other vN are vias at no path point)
3.3V: C6.1 C9.1 C10.1 C11.1 J3.1 J4.3 L1.1 R1.2 R2.2 R3.2 R4.2 R5.2 R9.2 R25.1 R31.2 U1.35 U1.46 | length 76.2
  Top Layer w0.3: -13.807,8.68 -13.807,9.161 U1.35@-13.064,9.904 ; U1.46@-7.407,12.732 -6.577,11.901 C11.1@-5.3,11.901
  Top Layer w0.5: v1(-25.3,19.352) v1(-23.826,19.352) ; v1(-23.6,5.3) -23.33,5.57 -22.611,5.57 -22.581,5.6 -22.581,10.557 -22.6,10.577 -22.6,11.817 R9.2@-22.565,11.852 v1(-23.184,11.852) ; R31.2@-19.45,7.4 -19.45,6.637 v1(-19.263,6.45) ; v1(-18.063,18.388) L1.1@-17.5,18.388 ; -13.807,8.68 -12.95,7.824 -12.95,6.85 C10.1@-12.9,6.8 C9.1@-12.9,5.366 -12.9,4.308 -12.607,4.015 v1(-12.279,4.015) C6.1@-11.35,4.015 -11.35,2.734 -10.9,2.284 J4.3@-10.9,2 ; C11.1@-5.3,11.901 -5.2,11.901 -5.15,11.951 -5.15,12.407 -4.757,12.8 v1(-4.75,12.8) ; v1(-4.75,14.501) -4.15,14.501 -4.1,14.551 R5.2@-4.1,14.6
  Bottom Layer w0.5: J3.1@-30.02,23.39 -28.705,22.075 -26.744,22.075 -25.3,20.631 v1(-25.3,19.352) -25.3,18 -23.184,15.884 v1(-23.184,11.852) ; v1(-23.826,19.352) -22.556,19.352 -21.592,18.388 v1(-18.063,18.388) ; v1(-23.6,5.3) -20.413,5.3 -18.113,7.6 v1(-12.95,7.6) ; v1(-12.279,4.015) -5.951,4.015 -4.75,5.217 v1(-4.75,14.501)
A1.65V: C16.1 C20.1 R10.2 R16.2 R20.2 R26.2 | length 37.1
  Top Layer w0.4: v1(-25.435,22.75) -25.417,22.732 -25.417,22.175 R10.2@-25.4,22.158 ; v1(-21.914,13.175) -21.905,13.184 -21.416,13.184 R20.2@-21.407,13.193 C16.1@-20.201,13.193 ; v1(-18.051,24.8) R16.2@-17.4,24.8 ; R26.2@-7.25,24.8 C20.1@-5.85,24.8 -5.835,24.785 -5.835,24.216 v1(-5.82,24.201)
  Bottom Layer w0.4: v1(-21.914,13.175) -21.914,15.533 -24.293,17.912 -24.293,17.924 -24.65,18.281 -24.65,20.906 -25.435,21.691 v1(-25.435,22.75) -25.435,23.415 -24.05,24.8 v1(-18.051,24.8) -6.419,24.8 v1(-5.82,24.201)
A3.3V: C8.1 C13.1 C21.1 L1.2 R18.2 U1.18 U2.8 U3.8 | length 20.9
  Top Layer w0.3: R18.2@-25.399,17.063 -24.687,17.063 -24.298,17.451 -23.027,17.451 -23.022,17.456 -21.752,17.456 ; U2.8@-21.752,16.181 -21.752,17.456 ; C13.1@-20.15,17.046 -20.162,17.034 -20.21,17.082 -20.774,17.082 -21.149,17.456 -21.752,17.456 ; C8.1@-16.3,19.6 -16.177,19.477 -15.75,19.477 -15.1,18.827 -15.1,18.304 U1.18@-14.478,17.682 ; C21.1@-16.2,20.9 -15.726,20.9 -15.221,21.405 -15.221,22.189 -14.984,22.425 U3.8@-14.575,22.425
  Top Layer w0.5: C13.1@-20.15,17.046 v1(-16.9,17.046) ; L1.2@-17.5,19.588 -17.488,19.6 v1(-16.9,19.6) C8.1@-16.3,19.6 -16.3,20.85 -16.25,20.9 C21.1@-16.2,20.9
  Bottom Layer w0.5: v1(-16.9,17.046) v1(-16.9,19.6)
BOOT_MODE: R9.1 S1.1 U1.27 | length 10
  Top Layer w0.2: S1.1@-24.6,11.81 -24.333,12.077 -23.917,12.077 -23.502,12.493 -21.482,12.493 -21.365,12.376 R9.1@-21.365,11.852 -21.266,11.753 -19.684,11.753 -19.306,12.131 -16.494,12.131 U1.27@-15.893,12.732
